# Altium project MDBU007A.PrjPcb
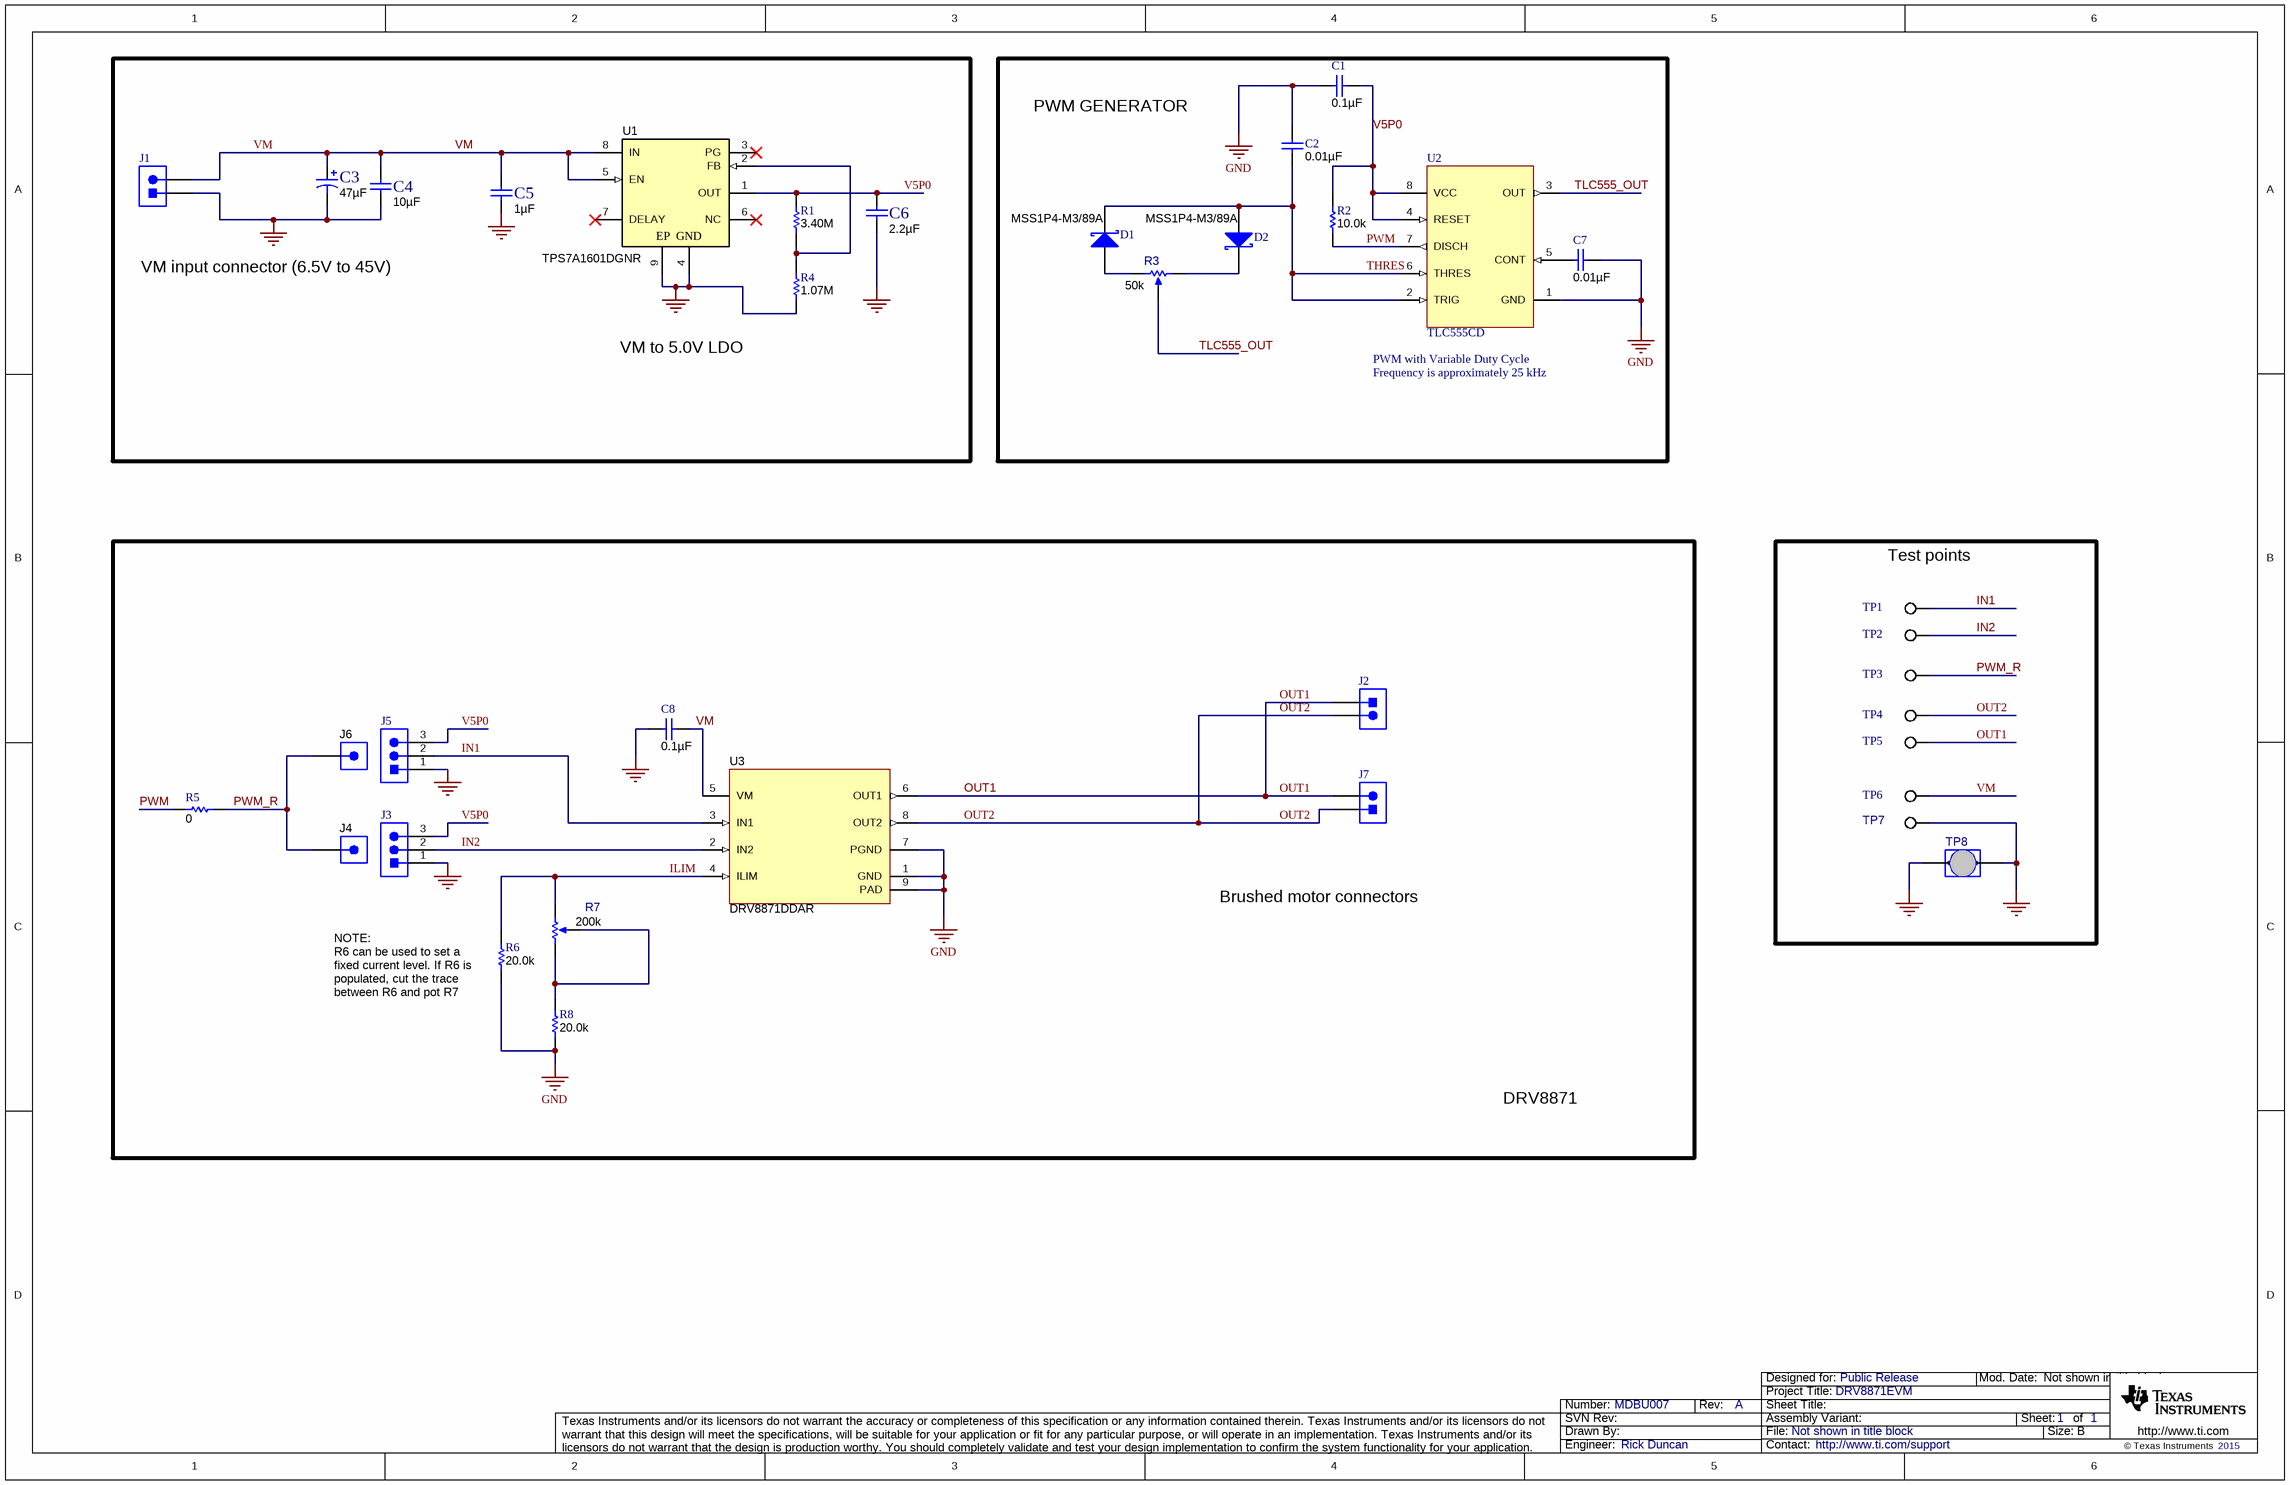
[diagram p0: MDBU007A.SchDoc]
CopyrightYear: 2015; PCB_Layout: Rick Duncan; PCB_Rev: A; PRJ_Customer: Public Release; PRJ_Engineer: Rick Duncan; PRJ_Number: MDBU007; PRJ_Title: DRV8871EVM; SCH_Rev: A; TechSupport: http://www.ti.com/support; TID: N/A
2 sheets, 54 parts. Net scope: global (net labels, ports and power ports of the same name join across sheets).
Board file: MDBU007A.PcbDoc
Sheets:
  MDBU007A.SchDoc
  MDBU007A_Hardware.SchDoc

## Sheet MDBU007A.SchDoc
size 431 x 279 mm; Date: Not shown in title block; ApprovedBy: Not shown in title block; CheckedBy: Not shown in title block; Author: Not shown in title block; CompanyName: Not shown in title block; Engineer: Not shown in title block; Organization: Not shown in title block; Address1: Not shown in title block; Address2: Not shown in title block; Address3: Not shown in title block; Address4: Not shown in title block; DocumentNumber: 1; Revision: Use project parameter SCH_Rev; SheetNumber: 1; SheetTotal: 1; PageSetup: Record=PageOptions¦CenterHorizontal=True¦CenterVertical=True¦PrintScale=0.61¦XCorrection=1.00¦YCorrection=1.00¦PrintKind=0¦BorderSize=5000000¦LeftOffset=0¦BottomOffset=0¦Orientation=2¦PaperLength=1000¦PaperWidth=1000¦Scale=100¦PaperSource=15¦PrintQuality=600¦MediaType=1¦DitherType=10¦PaperKind=Letter¦PrintScaleMode=1

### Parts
C1  ValueDisplayed: 0.1µF  [0603L]  (hidden comment: C0603C104M4RACTU)
C2  ValueDisplayed: 0.01µF  [0603L]  (hidden comment: C0603X103K5RACTU)
C3  ValueDisplayed: 47µF  [SM_RADIAL_F]  (hidden comment: EEE-FK1J470P)
C4  ValueDisplayed: 10µF  [1210_280]  (hidden comment: UMK325AB7106KM-T)
C5  ValueDisplayed: 1µF  [0805L]  (hidden comment: 08055C105KAT2A)
C6  ValueDisplayed: 2.2µF  [0603L]  (hidden comment: C0603C225K8PACTU)
C7  ValueDisplayed: 0.01µF  [0603L]  (hidden comment: C0603X103K5RACTU)
C8  ValueDisplayed: 0.1µF  [0805L]  (hidden comment: C0805C104K1RACTU)
D1  MSS1P4-M3/89A  [MicroSMP]
D2  MSS1P4-M3/89A  [MicroSMP]
J1  ED555/2DS  [TERM_BLK_ED555-2DS]  (value not drawn)
J2  ED555/2DS  [TERM_BLK_ED555-2DS]  (value not drawn)
J3  PEC03SAAN  [CONN_PEC03SAAN]  (value not drawn)
J4  PEC01SAAN  [Sullins_PEC01SAAN]  (value not drawn)
J5  PEC03SAAN  [CONN_PEC03SAAN]  (value not drawn)
J6  PEC01SAAN  [Sullins_PEC01SAAN]  (value not drawn)
J7  PEC02SAAN  [CONN_PEC02SAAN]  (value not drawn)
R1  ValueDisplayed: 3.40M  [0603L]  (hidden comment: CRCW06033M40FKEA)
R2  ValueDisplayed: 10.0k  [0603L]  (hidden comment: ERJ-3EKF1002V)
R3  value 50k  [BOURNS_3386P]  (hidden comment: 3386P-1-503TLF)
R4  ValueDisplayed: 1.07M  [0603L]  (hidden comment: CRCW06031M07FKEA)
R5  ValueDisplayed: 0  [0603L]  (hidden comment: CRCW06030000Z0EA)
R6  ValueDisplayed: 20.0k  [0402L]  (hidden comment: CRCW040220K0FKED)
R7  value 200k  [BOURNS_3386P]  (hidden comment: 3386P-1-204TLF)
R8  ValueDisplayed: 20.0k  [0402L]  (hidden comment: CRCW040220K0FKED)
TP1  5016  [Testpoint_Keystone_Compact]  (value not drawn)
TP2  5016  [Testpoint_Keystone_Compact]  (value not drawn)
TP3  5016  [Testpoint_Keystone_Compact]  (value not drawn)
TP4  5016  [Testpoint_Keystone_Compact]  (value not drawn)
TP5  5016  [Testpoint_Keystone_Compact]  (value not drawn)
TP6  5016  [Testpoint_Keystone_Compact]  (value not drawn)
TP7  GND  [Testpoint_Keystone_Compact]  (value not drawn)
TP8  D3082-05  [Harwin_D3082-05]  (value not drawn)
U1  TPS7A1601DGNR  [DGN0008C_L]
U2  TLC555CD  [D0008A_L]
U3  DRV8871DDAR  [DDA0008H_L]

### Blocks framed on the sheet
PWM GENERATOR: C1 C2 C7 D1 D2 R2 R3 U2
Test points: TP1-TP8

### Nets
GND: C1.1 C2.1 C3.2(-) C4.2 C5.2 C6.2 C7.1 C8.1 J1.1 J3.1 J5.1 R4.1 R6.2 R8.2 TP7.1 TP8.1 TP8.2 U1.4(GND) U1.9(EP) U2.1(GND) U3.1(GND) U3.7(PGND) U3.9(PAD)
ILIM: R6.1 R7.3(CW) U3.4(ILIM)
IN1: J5.2 TP1.1 U3.3(IN1)
IN2: J3.2 TP2.1 U3.2(IN2)
OUT1: J2.1 J7.2 TP5.1 U3.6(OUT1)
OUT2: J2.2 J7.1 TP4.1 U3.8(OUT2)
PWM: R2.1 R5.2 U2.7(DISCH)
PWM_R: J4.1 J6.1 R5.1 TP3.1
THRES: C2.2 D1.1(K) D2.2(A) U2.2(TRIG) U2.6(THRES)
TLC555_OUT: R3.2(WIPER) U2.3(OUT)
V5P0: C1.2 C6.1 J3.3 J5.3 R1.2 R2.2 U1.1(OUT) U2.4(RESET) U2.8(VCC)
VM: C3.1(+) C4.1 C5.1 C8.2 J1.2 TP6.1 U1.5(EN) U1.8(IN) U3.5(VM)
NetC7_2: C7.2 U2.5(CONT)
NetD1_2: D1.2(A) R3.1(CCW)
NetD2_1: D2.1(K) R3.3(CW)
NetR1_1: R1.1 R4.2 U1.2(FB)
NetR7_1: R7.1(CCW) R7.2(WIPER) R8.1

Not connected (* = marked no-connect by the designer): U1 3(PG)* 6(NC)* 7(DELAY)*

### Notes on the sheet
- VM input connector (6.5V to 45V)
- VM to 5.0V LDO
- PWM with Variable Duty Cycle
- Frequency is approximately 25 kHz
- Brushed motor connectors
- (near R6) NOTE:
  R6 can be used to set a fixed current level. If R6 is populated, cut the trace between R6 and pot R7
- DRV8871

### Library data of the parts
C1 = C0603C104M4RACTU: CAP, CERM, 0.1 µF, 16 V, +/- 20%, X7R, 0603; Manufacturer: Kemet; Value: 0.1uF; Polarized: N; CompType: Capacitor; U/M: EA; Cap_F: 0.0000001; Tolerance_%: 20; Value1: Unknown; VDC_V: 16; Value2: 16V; TaMin_C: -55; TaMax_C: 125; Cap_Case: 0603
C2 C7 = C0603X103K5RACTU: CAP, CERM, 0.01 µF, 50 V, +/- 10%, X7R, 0603; Manufacturer: Kemet; Value: 0.01uF; Polarized: N; CompType: Capacitor; U/M: EA; Cap_F: 0.00000001; Tolerance_%: 10; Value1: Unknown; VDC_V: 50; Value2: 50V; TaMin_C: -55; TaMax_C: 125; Cap_Case: 0603
C3 = EEE-FK1J470P: CAP, AL, 47 µF, 63 V, +/- 20%, 0.65 ohm, SMD; Manufacturer: Panasonic; Value: 47uF; Polarized: Y; CompType: Capacitor; U/M: EA; Cap_F: 0.000047; Tolerance_%: 20; VDC_V: 63; Value2: 63V; ESR_ohm: 0.65; IRMS_A: 0.25; TaMin_C: -55; TaMax_C: 105; Cap_Case: F
C4 = UMK325AB7106KM-T: CAP, CERM, 10 µF, 50 V, +/- 10%, X7R, 1210; Manufacturer: Taiyo Yuden; Value: 10uF; Polarized: N; CompType: Capacitor; U/M: EA; Cap_F: 0.00001; Tolerance_%: 10; Value1: Unknown; VDC_V: 50; Value2: 50V; TaMin_C: -55; TaMax_C: 125; Cap_Case: 1210
C5 = 08055C105KAT2A: CAP, CERM, 1 µF, 50 V, +/- 10%, X7R, 0805; Manufacturer: AVX; Value: 1uF; Polarized: N; CompType: Capacitor; U/M: EA; Cap_F: 0.000001; Tolerance_%: 10; Value1: Unknown; VDC_V: 50; Value2: 50V; TaMin_C: -55; TaMax_C: 125; Cap_Case: 0805
C6 = C0603C225K8PACTU: CAP, CERM, 2.2uF, 10V, +/-10%, X5R, 0603; Manufacturer: Kemet; Polarized: N; CompType: Capacitor; U/M: EA; Cap_F: 0.0000022; Tolerance_%: 10; Value1: Unknown; TaMin_C: -55; TaMax_C: 85; Cap_Case: 0603
C8 = C0805C104K1RACTU: CAP, CERM, 0.1 µF, 100 V, +/- 10%, X7R, 0805; Manufacturer: Kemet; Value: 0.1uF; Polarized: N; CompType: Capacitor; U/M: EA; Cap_F: 0.0000001; Tolerance_%: 10; ESR_ohm: 0.064; Value1: 0.064 ohm; VDC_V: 100; Value2: 100V; IRMS_A: 1.64; TaMin_C: -55; TaMax_C: 125; Cap_Case: 0805
D1 D2 = MSS1P4-M3/89A: Diode, Schottky, 40 V, 1 A, MicroSMP; Manufacturer: Vishay-Siliconix; Value: 40V; U/M: EA; Vf_V: 0.55; Value1: 1A; Value2: 0.55V; Io_A: 1; Vr_V: 40; TJmax_C: 150
J1 J2 = ED555/2DS: Terminal Block, 6A, 3.5mm Pitch, 2-Pos, TH; Manufacturer: On-Shore Technology; SymbolCreator: a0412235; CompType: Connector; U/M: EA
J3 J5 = PEC03SAAN: Header, 100mil, 3x1, Tin, TH; Manufacturer: Sullins Connector Solutions; U/M: EA; SymbolCreator: a0799628
J4 J6 = PEC01SAAN: Header, 1x1, Tin, TH; Manufacturer: Sullins Connector Solutions; SymbolCreator: a0412235; U/M: EA
J7 = PEC02SAAN: Header, 100mil, 2x1, Tin, TH; Manufacturer: Sullins Connector Solutions; SymbolCreator: a0412235; U/M: EA
R1 = CRCW06033M40FKEA: RES, 3.40 M, 1%, 0.1 W, 0603; Manufacturer: Vishay-Dale; Value: 3.40Meg; CompType: Resistor; Res_ohm: 3400000; Value_Code: 3M40; Tolerance_%: 1; Power_W: 0.1; Value2: 0.1W; VDC_V: 75; TempCo: 100 ppm/C; EIA_Code: E96; U/M: EA
R2 = ERJ-3EKF1002V: RES, 10.0 k, 1%, 0.1 W, 0603; Manufacturer: Panasonic; Value: 10.0k; CompType: Resistor; Res_ohm: 10000; Value_Code: 10k0; Tolerance_%: 1; Power_W: 0.1; Value2: 0.1W; VDC_V: 75; TempCo: 100 ppm/C; EIA_Code: E96; U/M: EA
R3 = 3386P-1-503LF: TRIMMER, 50k ohm, 0.5W, TH; Manufacturer: Bourns; Sim Note: Enter the Resistance value and the set point into parameter fields.; SymbolCreator: a0412235
R4 = CRCW06031M07FKEA: RES, 1.07 M, 1%, 0.1 W, 0603; Manufacturer: Vishay-Dale; Value: 1.07Meg; CompType: Resistor; Res_ohm: 1070000; Value_Code: 1M07; Tolerance_%: 1; Power_W: 0.1; Value2: 0.1W; VDC_V: 75; TempCo: 100 ppm/C; EIA_Code: E96; U/M: EA
R5 = CRCW06030000Z0EA: RES, 0, 5%, 0.1 W, 0603; Manufacturer: Vishay-Dale; Value: 0; CompType: Resistor; Value_Code: 0000; Tolerance_%: 5; Power_W: 0.1; Value2: 0.1W; VDC_V: 75; TempCo: 200 ppm/C; EIA_Code: E24; U/M: EA
R6 R8 = CRCW040220K0FKED: RES, 20.0 k, 1%, 0.063 W, 0402; Manufacturer: Vishay-Dale; Value: 20.0k; CompType: Resistor; Res_ohm: 20000; Value_Code: 20k0; Tolerance_%: 1; Power_W: 0.063; Value2: 0.063W; VDC_V: 50; TempCo: 100 ppm/C; EIA_Code: E96; U/M: EA
R7 = 3386P-1-204LF: TRIMMER, 200k ohm, 0.5W, TH; Manufacturer: Bourns; Sim Note: Enter the Resistance value and the set point into parameter fields.; SymbolCreator: a0412235
TP1-TP7 = 5016: Test Point, Compact, SMT; Manufacturer: Keystone; CompType: Test Point Loop; U/M: EA
TP8 = D3082-05: 1mm Uninsulated Shorting Plug, 10.16mm spacing, TH; Manufacturer: Harwin; SymbolCreator: a0799628; CompType: Jumper Wire; U/M: EA
U1 = TPS7A1601DGNR: Single Output LDO, 100 mA, Adjustable 1.2 to 18.5 V Output, 3 to 60 V Input, with Enable and Power Good, 8-pin MSOP (DGN), -40 to 125 degC, Green (RoHS & no Sb/Br); Manufacturer: Texas Instruments; Alternate PartNumber: Equivalent; Accuracy(%): 2; Iout(Max)(A): 0.1; Iq(Typ)(mA): 0.004; Power Good: TRUE; Rating: Catalog; SubFamily: Single Channel LDO; Vdo(Typ)(mV): 60; Vin(Min)(V): 3; Vout Adj(Max)(V): 18.5; Vout Adj(Min)(V): 1.2
U2 = TLC555CD: LinCMOS Timer, D0008A; Manufacturer: Texas Instruments; SymbolCreator: a0799628; CompType: IC; U/M: EA
U3 = DRV8871DDAR: H-Bridge PWM Motor Driver with Internal Current Sense, DDA0008H; Manufacturer: Texas Instruments; SymbolCreator: Altium; CompType: IC; U/M: EA

## Sheet MDBU007A_Hardware.SchDoc
size 431 x 279 mm; Date: Not shown in title block; ApprovedBy: Not shown in title block; CheckedBy: Not shown in title block; Author: Not shown in title block; CompanyName: Not shown in title block; Engineer: Not shown in title block; Organization: Not shown in title block; Address1: Not shown in title block; Address2: Not shown in title block; Address3: Not shown in title block; Address4: Not shown in title block; DocumentNumber: 1; Revision: Use project parameter SCH_Rev; SheetNumber: 3; SheetTotal: 3; PageSetup: Record=PageOptions¦CenterHorizontal=True¦CenterVertical=True¦PrintScale=1.00¦XCorrection=1.00¦YCorrection=1.00¦PrintKind=0¦BorderSize=5000000¦LeftOffset=0¦BottomOffset=0¦Orientation=2¦PaperLength=1000¦PaperWidth=1000¦Scale=100¦PaperSource=15¦PrintQuality=600¦MediaType=1¦DitherType=10¦PaperKind=Letter¦PrintScaleMode=1
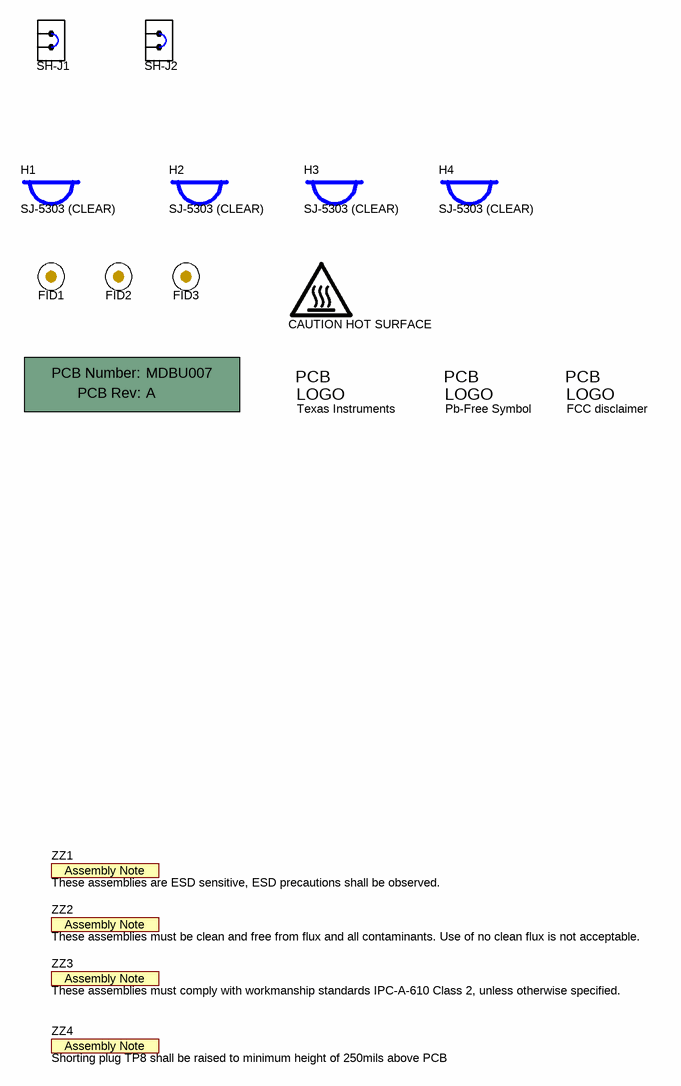
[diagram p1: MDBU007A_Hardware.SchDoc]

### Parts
!PCB  Printed Circuit Board  (value not drawn)  (mechanical)
FID1  Fiducial  [Fiducial10-20]  (value not drawn)
FID2  Fiducial  [Fiducial10-20]  (value not drawn)
FID3  Fiducial  [Fiducial10-20]  (value not drawn)
H1  SJ-5303 (CLEAR)  [Bumpon_SJ5003Transparent]
H2  SJ-5303 (CLEAR)  [Bumpon_SJ5003Transparent]
H3  SJ-5303 (CLEAR)  [Bumpon_SJ5003Transparent]
H4  SJ-5303 (CLEAR)  [Bumpon_SJ5003Transparent]
LOGO1  CAUTION HOT SURFACE  [IEC_HotSurface_Small]  (no BOM)
Logo2  Texas Instruments  [TI_Stacked_Overlay_Small]  (no BOM)
Logo3  Pb-Free Symbol  [Pb-Free_Overlay_Small]  (no BOM)
Logo4  FCC disclaimer  [FCC_disclaimer]  (no BOM)
SH-J1  969102-0000-DA  [SNT-100-BK-G]  (value not drawn)
SH-J2  969102-0000-DA  [SNT-100-BK-G]  (value not drawn)
ZZ1  These assemblies are ESD sensitive, ESD precautions shall be observed.  [AssemblyNote]  (no BOM)
ZZ2  These assemblies must be clean and free from flux and all contaminants. Use of no clean flux is not acceptable.  [AssemblyNote]  (no BOM)
ZZ3  These assemblies must comply with workmanship standards IPC-A-610 Class 2, unless otherwise specified.  [AssemblyNote]  (no BOM)
ZZ4  Shorting plug TP8 shall be raised to minimum height of 250mils above PCB  [AssemblyNote]  (no BOM)

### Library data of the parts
!PCB = PCB: Manufacturer: Any; PartNumber: MDBU007; SymbolCreator: a0412235
FID1-FID3 = Fiducial: Fiducial mark.  There is nothing to buy or mount.; SymbolCreator: codlsc
H1-H4 = SJ-5303 (CLEAR): Bumpon, Hemisphere, 0.44 X 0.20, Clear; Manufacturer: 3M; SymbolCreator: a0412235
LOGO1 = IEC_HotSurface: IEC 61010-1 Hot Surface Warning; SymbolCreator: a0412235
Logo2 = TI_Logo: Texas Instrument Corporate Signature; SymbolCreator: codlsc
Logo3 = Pb-Free: SymbolCreator: a0412235
Logo4 = FCC_disclaimer: SymbolCreator: codlsc
SH-J1 SH-J2 = 969102-0000-DA: Shunt, 100mil, Gold plated, Black; Manufacturer: 3M; Alternate Manufacturer: Samtec; Value: 1x2; Note: You can "mate" this to a header by matching the designator.  i.e. use SH-J3 for header J3
ZZ1-ZZ4 = AssemblyNote: SymbolCreator: codlsc

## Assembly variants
001: not fitted FID1 FID2 FID3 R6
